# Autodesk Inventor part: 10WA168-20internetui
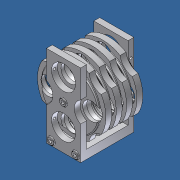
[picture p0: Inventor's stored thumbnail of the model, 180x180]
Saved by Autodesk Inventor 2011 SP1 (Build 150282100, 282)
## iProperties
Created: 2011-11
Part Number: 10WA168-20internetui
Document SubType Name: Modeling
Designer: Darius
Density: 1 g/cm^3
Author: Darius
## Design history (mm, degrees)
feature "Base1"
body "Solid1"
